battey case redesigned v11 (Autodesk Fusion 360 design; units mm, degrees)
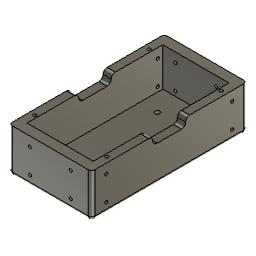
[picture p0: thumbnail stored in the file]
sketch "草图1" plane through (0, 0, 0) normal (0, 0, 1) x axis (1, 0, 0)
  line L1 (10.375, 38.4) -> (11.025, 38.4)
  line L2 (-14.9, 2.65) -> (-18.5, 2.65)
  line L3 (-18.5, -36.5) -> (-20, -36.5)
  line L4 (16, 3.65) -> (20, 3.65)
  line L5 (-14, 39.6) -> (-14, 40)
  line L6 (18.5, -36.1) -> (14, -36.1)
  line L7 (8.875, -34.7) -> (8.875, -34.9)
  line L8 (-11.025, 40) -> (-11.025, 38.4)
  line L9 (-14.9, 0.85) -> (-14.9, 2.65)
  line L10 (-8.875, -34.7) -> (-10.375, -34.7)
  line L11 (-18.5, 0.85) -> (-14.9, 0.85)
  line L12 (10.375, 38.2) -> (10.375, 38.4)
  line L13 (-20, -0.15) -> (-20, 3.65)
  line L14 (-20, -7.55) -> (-16, -7.55)
  line L15 (18.5, 38.5) -> (14.9, 38.5)
  line L16 (8.225, 40) -> (8.225, 38.4)
  line L17 (10.375, -34.9) -> (10.375, -34.7)
  line L18 (-8.225, -36.5) -> (-8.225, -34.9)
  line L19 (8.225, 38.4) -> (8.875, 38.4)
  line L20 (11.025, 40) -> (14, 40)
  line L21 (-16, -7.55) -> (-16, -0.15)
  line L22 (14, -36.1) -> (14, -36.5)
  line L23 (-18.5, 38.5) -> (-18.5, 12.55)
  line L24 (-16, 11.05) -> (-20, 11.05)
  line L25 (-16, 3.65) -> (-16, 11.05)
  line L26 (-18.5, 12.55) -> (-14.9, 12.55)
  line L27 (-18.5, 2.65) -> (-18.5, 0.85)
  line L28 (20, 3.65) -> (20, -0.15)
  line L29 (0.75, -36.5) -> (-0.75, -36.5)
  line L30 (20, -36.5) -> (18.5, -36.5)
  line L31 (11.025, 38.4) -> (11.025, 40)
  line L32 (16, -0.15) -> (16, -7.55)
  line L33 (14.9, 38.5) -> (14.9, 12.55)
  line L34 (20, 40) -> (20, 11.05)
  line L35 (-14.9, 12.55) -> (-14.9, 38.5)
  line L36 (14.9, -9.05) -> (14.9, -35)
  line L37 (20, -7.55) -> (20, -36.5)
  line L38 (20, 11.05) -> (16, 11.05)
  line L39 (14.9, 12.55) -> (18.5, 12.55)
  line L40 (-11.025, -36.5) -> (-14, -36.5)
  line L41 (16, -7.55) -> (20, -7.55)
  line L42 (14, 39.6) -> (18.5, 39.6)
  line L43 (18.5, 0.85) -> (18.5, 2.65)
  line L44 (20, -0.15) -> (16, -0.15)
  line L45 (8.225, -36.5) -> (5.25, -36.5)
  line L46 (18.5, -9.05) -> (14.9, -9.05)
  line L47 (18.5, 39.6) -> (18.5, 40)
  line L48 (18.5, 2.65) -> (14.9, 2.65)
  line L49 (-20, -36.5) -> (-20, -7.55)
  line L50 (-18.5, -9.05) -> (-18.5, -35)
  line L51 (14.9, 2.65) -> (14.9, 0.85)
  line L52 (5.25, 39.6) -> (5.25, 40)
  line L53 (5.25, 40) -> (8.225, 40)
  line L54 (18.5, 40) -> (20, 40)
  line L55 (14, 40) -> (14, 39.6)
  line L56 (14, -36.5) -> (11.025, -36.5)
  line L57 (14.9, 0.85) -> (18.5, 0.85)
  line L58 (0.75, 39.6) -> (5.25, 39.6)
  line L59 (5.25, -36.1) -> (0.75, -36.1)
  line L60 (8.225, -34.9) -> (8.225, -36.5)
  line L61 (11.025, -36.5) -> (11.025, -34.9)
  line L62 (-14, 40) -> (-11.025, 40)
  line L63 (18.5, 12.55) -> (18.5, 38.5)
  line L64 (16, 11.05) -> (16, 3.65)
  line L65 (-14.9, -35) -> (-14.9, -9.05)
  line L66 (18.5, -35) -> (18.5, -9.05)
  line L67 (-20, 11.05) -> (-20, 40)
  line L68 (-0.75, -36.1) -> (-5.25, -36.1)
  line L69 (-5.25, -36.1) -> (-5.25, -36.5)
  line L70 (-10.375, 38.2) -> (-8.875, 38.2)
  line L71 (8.875, 38.2) -> (10.375, 38.2)
  line L72 (-0.75, 39.6) -> (-0.75, 40)
  line L73 (-14.9, -9.05) -> (-18.5, -9.05)
  line L74 (-10.375, 38.4) -> (-10.375, 38.2)
  line L75 (-20, 3.65) -> (-16, 3.65)
  line L76 (-18.5, 40) -> (-18.5, 39.6)
  line L77 (8.875, 38.4) -> (8.875, 38.2)
  line L78 (-14.9, 38.5) -> (-18.5, 38.5)
  line L79 (8.875, -34.9) -> (8.225, -34.9)
  line L80 (11.025, -34.9) -> (10.375, -34.9)
  line L81 (10.375, -34.7) -> (8.875, -34.7)
  line L82 (0.75, -36.1) -> (0.75, -36.5)
  line L83 (5.25, -36.5) -> (5.25, -36.1)
  line L84 (-5.25, -36.5) -> (-8.225, -36.5)
  line L85 (-10.375, -34.9) -> (-11.025, -34.9)
  line L86 (-20, 40) -> (-18.5, 40)
  line L87 (-16, -0.15) -> (-20, -0.15)
  line L88 (-5.25, 40) -> (-5.25, 39.6)
  line L89 (-18.5, -36.1) -> (-18.5, -36.5)
  line L90 (18.5, -36.5) -> (18.5, -36.1)
  line L91 (14.9, -35) -> (18.5, -35)
  line L92 (-18.5, -35) -> (-14.9, -35)
  line L93 (-8.225, 38.4) -> (-8.225, 40)
  line L94 (0.75, 40) -> (0.75, 39.6)
  line L95 (-0.75, -36.5) -> (-0.75, -36.1)
  line L96 (-8.875, 38.4) -> (-8.225, 38.4)
  line L97 (-11.025, -34.9) -> (-11.025, -36.5)
  line L98 (-8.875, 38.2) -> (-8.875, 38.4)
  line L99 (-8.225, -34.9) -> (-8.875, -34.9)
  line L100 (-14, -36.5) -> (-14, -36.1)
  line L101 (-5.25, 39.6) -> (-0.75, 39.6)
  line L102 (-11.025, 38.4) -> (-10.375, 38.4)
  line L103 (-10.375, -34.7) -> (-10.375, -34.9)
  line L104 (-0.75, 40) -> (0.75, 40)
  line L105 (-18.5, 39.6) -> (-14, 39.6)
  line L106 (-8.225, 40) -> (-5.25, 40)
  line L107 (-8.875, -34.9) -> (-8.875, -34.7)
  line L108 (-14, -36.1) -> (-18.5, -36.1)
  line L109 (20, 40) -> (-20, 40)
  line L110 (20, -36.5) -> (20, 40)
  line L111 (-20, -36.5) -> (20, -36.5)
  line L112 (-20, 40) -> (-20, -36.5)
  line L113 (-22.25, 42.25) -> (-22.25, -38.75)
  line L114 (22.25, 42.25) -> (-22.25, 42.25)
  line L115 (22.25, -38.75) -> (22.25, 42.25)
  line L116 (-22.25, -38.75) -> (22.25, -38.75)
  line L117 (20.25, 40.25) -> (-20.25, 40.25)
  line L118 (20.25, -36.75) -> (20.25, 40.25)
  line L119 (-20.25, -36.75) -> (20.25, -36.75)
  line L120 (-20.25, 40.25) -> (-20.25, -36.75)
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  point P44 (-20, 40)
  point P119 (20, 40)
  point P91 (20, -36.5)
  point P16 (-9.5, 29.25)
  point P24 (-9.5, -25.75)
  point P28 (-9.5, 29.25)
  point P26 (9.5, 29.25)
  point P25 (9.5, -25.75)
  horizontal L109
  vertical L110
  horizontal L111
  vertical L112
  dimension "d1" distance P44 P119 = 40
  dimension "d2" distance P91 P119 = 76.5
  dimension "d3" distance P16 L67 = 10.5
  dimension "d4" distance P24 P28 = 55
  dimension "d5" distance P26 P28 = 19
  dimension "d6" distance P26 L34 = 10.5
  dimension "d7" distance P25 P26 = 55
  dimension "d8" distance P24 P25 = 19
  dimension "d9" distance P28 L109 = 10.75
  dimension "d10" diameter = 2.95
  dimension "d11" distance = 1
  dimension "d12" = -2.25
  dimension "d15" = -0.25
extrude "拉伸1" new body sketch "草图1" along normal blind 3
sketch "草图2" plane through (0, 0, 3) normal (0, 0, 1) x axis (-1, 0, 0)
  line L1 (-20.25, 36.75) -> (20.25, 36.75)
  line L2 (-20.25, -40.25) -> (-20.25, 36.75)
  line L3 (20.25, -40.25) -> (-20.25, -40.25)
  line L4 (20.25, 36.75) -> (20.25, -40.25)
  line L5 (-20.25, 36.75) -> (20.25, -40.25)
  line L6 (20.25, 36.75) -> (-20.25, -40.25)
  line L7 (20.25, 43.75) -> (-20.25, 43.75)
  line L8 (20.25, -47.25) -> (20.25, 43.75)
  line L9 (-20.25, -47.25) -> (20.25, -47.25)
  line L10 (-20.25, 43.75) -> (-20.25, -47.25)
  line L11 (20.25, -47.25) -> (-20.25, 43.75)
  line L12 (-20.25, -47.25) -> (20.25, 43.75)
  line L13 (-22.25, -49.25) -> (22.25, -49.25)
  line L14 (-22.25, 45.75) -> (-22.25, -49.25)
  line L15 (22.25, 45.75) -> (-22.25, 45.75)
  line L16 (22.25, -49.25) -> (22.25, 45.75)
  circle C1 centre (-9.5, -29.25) radius 1.475
  circle C2 centre (-9.5, 25.75) radius 1.475
  circle C3 centre (9.5, -29.25) radius 1.475
  circle C4 centre (9.5, 25.75) radius 1.475
  point P8 (20.25, -40.25)
  point P10 (20.25, -40.25)
  point P6 (-20.25, 36.75)
  point P11 (-20.25, 36.75)
  point P7 (-20.25, -40.25)
  point P12 (-20.25, -40.25)
  point P5 (20.25, 36.75)
  point P13 (20.25, 36.75)
  point P18 (0, -1.75)
  coincident P8 P10
  coincident P6 P11
  coincident P7 P12
  coincident P5 P13
  horizontal L7
  perpendicular L7 L8
  parallel L7 L9
  parallel L8 L10
  coincident L11 P18
  coincident L12 P18
  midpoint L5 P18
  collinear L2 L10
  dimension "d18" distance L3 L9 = 7
  dimension "d19" = -2
extrude "拉伸3" add sketch "草图2" profile of L1 L3 L7 L8 L9 L10 against normal blind 3
extrude "拉伸4" sketch "草图2" profile of L2 L4 L7 L8 L9 L10 L16 L13 L15 L14 blind 26.5 (= "23.5 mm + 3 mm")
sketch "草图3" plane through (22.25, 0, 0) normal (1, 0, 0) x axis (0, 1, 0)
  line L1 (49.25, 0) -> (-45.75, 0)
  line L2 (49.25, 26.5) -> (49.25, 0)
  line L3 (-45.75, 26.5) -> (49.25, 26.5)
  line L4 (-45.75, 0) -> (-45.75, 26.5)
  line L5 (1.75, 0) -> (1.75, 26.5)
  line L6 (49.25, 13.25) -> (1.75, 13.25)
  circle C1 centre (40.25, 20.75) radius 0.95
  circle C2 centre (-36.75, 20.75) radius 0.95
  circle C3 centre (40.25, 5.75) radius 0.95
  circle C4 centre (-36.75, 5.75) radius 0.95
  point P6 (1.75, 26.5)
  point P7 (1.75, 0)
  point P8 (1.75, 13.25)
  point P9 (49.25, 13.25)
  point P10 (40.25, 20.75)
  point P12 (40.25, 5.75)
  point P13 (-36.75, 5.75)
  midpoint L3 P6
  midpoint L1 P7
  midpoint L5 P8
  midpoint L2 P9
  symmetric L5 C1 C2
  symmetric L6 C1 C3
  symmetric L6 C2 C4
  dimension "d25" diameter C1 = 1.9
  dimension "d26" distance P10 P12 = 15
  dimension "d27" distance P12 P13 = 77
extrude "拉伸5" add sketch "草图3" profile of L1 L2 L3 L4 C1 C2 C3 C4 along normal blind 3
extrude "拉伸9" of existing geometry blind -3
extrude "拉伸10" cut of existing geometry blind -2
extrude "拉伸6" cut of existing geometry blind -2
extrude "拉伸11" add of existing geometry blind 4
extrude "拉伸12" add of existing geometry blind 4
sketch "草图5" plane through (0, 49.25, 0) normal (0, 1, 0) x axis (-1, 0, 0)
  line L1 (25.25, 0) -> (-25.25, 0)
  line L2 (25.25, 26.5) -> (25.25, 0)
  line L3 (-25.25, 26.5) -> (25.25, 26.5)
  line L4 (-25.25, 0) -> (-25.25, 26.5)
  line L5 (0, 0) -> (0, 26.5)
  line L6 (25.25, 13.25) -> (-25.25, 13.25)
  circle C1 centre (12.5, 20.75) radius 0.95
  circle C2 centre (25.25, 20.75) radius 0.95
  circle C3 centre (12.5, 5.75) radius 0.95
  circle C4 centre (-12.5, 20.75) radius 0.95
  circle C5 centre (-12.5, 5.75) radius 0.95
  point P6 (0, 26.5)
  point P1 (0, 0)
  point P7 (0, 0)
  point P8 (-25.25, 13.25)
  point P9 (25.25, 13.25)
  point P10 (12.5, 20.75)
  point P12 (12.5, 5.75)
  point P13 (-12.5, 20.75)
  midpoint L3 P6
  coincident P1 P7
  midpoint L4 P8
  midpoint L2 P9
  equal C1 C2
  symmetric L6 C1 C3
  symmetric L5 C1 C4
  symmetric L5 C3 C5
  dimension "d54" distance P10 P12 = 15
  dimension "d55" distance P10 P13 = 25
extrude "拉伸13" cut sketch "草图5" profile of C1 C3 C4 C5 against normal blind 95
sketch "草图6" plane through (0, 0, 26.5) normal (0, 0, 1) x axis (-1, 0, 0)
  line L1 (-20.25, 39.75) -> (-20.25, -43.25)
  line L2 (20.25, 39.75) -> (-20.25, 39.75)
  line L3 (20.25, -43.25) -> (20.25, 39.75)
  line L4 (-20.25, -43.25) -> (20.25, -43.25)
  line L5 (25.25, -49.25) -> (-25.25, -49.25)
  line L6 (25.25, 45.75) -> (25.25, -49.25)
  line L7 (-25.25, 45.75) -> (25.25, 45.75)
  line L8 (-25.25, -49.25) -> (-25.25, 45.75)
  line L9 (25.25, -1.75) -> (-25.25, -1.75)
  line L10 (0, -49.25) -> (0, 45.75)
  circle C1 centre (22, 33.25) radius 0.975
  circle C2 centre (-22, 33.25) radius 0.975
  circle C3 centre (22, -36.75) radius 0.975
  circle C4 centre (-22, -36.75) radius 0.975
  point P10 (-25.25, -1.75)
  point P11 (25.25, -1.75)
  point P12 (0, 45.75)
  point P13 (0, -49.25)
  point P14 (22, 33.25)
  point P15 (-22, 33.25)
  point P17 (22, -36.75)
  midpoint L8 P10
  midpoint L6 P11
  midpoint L7 P12
  midpoint L5 P13
  symmetric L10 C1 C2
  symmetric L9 C1 C3
  symmetric L9 C2 C4
  dimension "d58" diameter C1 = 1.95
  dimension "d59" distance P14 P15 = 44
  dimension "d60" distance P14 P17 = 70
extrude "拉伸14" cut sketch "草图6" profile of C1 C2 C3 C4 against normal blind 6
extrude "拉伸15" sketch "草图6" profile of C1 C2 C3 C4 blind 6
sketch "草图7" plane through (-25.25, 0, 0) normal (-1, 0, 0) x axis (0, -1, 0)
  line L1 (45.75, 0) -> (-49.25, 0)
  line L2 (45.75, 26.5) -> (45.75, 0)
  line L3 (-49.25, 26.5) -> (45.75, 26.5)
  line L4 (-49.25, 0) -> (-49.25, 26.5)
  line L5 (-1.75, 0) -> (-1.75, 26.5)
  line L6 (-11.75, 21.5) -> (8.25, 21.5)
  line L7 (-11.75, 26.5) -> (-11.75, 21.5)
  line L8 (8.25, 26.5) -> (-11.75, 26.5)
  line L9 (8.25, 21.5) -> (8.25, 26.5)
  line L10 (-11.75, 26.5) -> (8.25, 21.5)
  line L11 (8.25, 26.5) -> (-11.75, 21.5)
  circle C1 centre (-40.25, 20.75) radius 0.95
  circle C2 centre (-40.25, 5.75) radius 0.95
  circle C3 centre (36.75, 20.75) radius 0.95
  circle C4 centre (36.75, 5.75) radius 0.95
  point P10 (-1.75, 26.5)
  point P11 (-1.75, 0)
  point P16 (-1.75, 24)
  point P12 (8.25, 21.5)
  point P15 (8.25, 26.5)
  point P13 (-11.75, 21.5)
  midpoint L3 P10
  midpoint L1 P11
  horizontal L6
  perpendicular L6 L7
  parallel L6 L8
  parallel L7 L9
  coincident L10 P16
  coincident L11 P16
  coincident L5 P16
  collinear L3 L8
  dimension "d68" distance P12 P15 = 5
  dimension "d69" distance P12 P13 = 20
extrude "拉伸16" cut sketch "草图7" profile of L3 L6 L7 L8 L9 against normal blind 50.5
fillet "圆角5" radius 2
fillet "圆角6" radius 2.5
